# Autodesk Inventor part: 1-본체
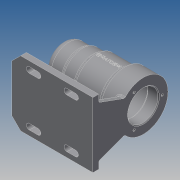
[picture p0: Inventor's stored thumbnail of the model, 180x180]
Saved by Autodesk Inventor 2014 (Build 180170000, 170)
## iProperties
Created: 2017-09
Part Number: 1-본체
Material: Generic
Document SubType Name: Modeling
Designer: kb542-00
Density: 1 g/cm^3
Appearance: Default
Author: kb542-00
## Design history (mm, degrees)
sketch "스케치1"
  geometry: L1 (-112, 0)-(0, 0); L2 (0, 21)-(0, 34); L3 (0, 34)-(-28, 34); L4 (-28, 34)-(-28, 30); L5 (-28, 30)-(-67, 30); L6 (-67, 30)-(-67, 27); L7 (-67, 27)-(-87, 27); L8 (-87, 27)-(-87, 25); L9 (-87, 25)-(-112, 25); L10 (-112, 25)-(-112, 0); L11 (-106, 0)-(-106, 10.5); L12 (-106, 10.5)-(-103, 10.5); L13 (-103, 10.5)-(-103, 16); L14 (-103, 16)-(-99, 16); L15 (-99, 16)-(-99, 17.5); L16 (-99, 17.5)-(-81, 17.5); L17 (-81, 17.5)-(-81, 21); L18 (-81, 21)-(-69, 21); L19 (-69, 21)-(-69, 24); L20 (-69, 24)-(-15, 24); L21 (-15, 24)-(-15, 21); L22 (-15, 21)-(0, 21); 1 further point
  constraints: 44 end point, 15 parallel, 6 perpendicular, 1 coincident, 1 horizontal, 1 point on line, 1 vertical alignment
  dimensions: "d0" = 68 diameter of L3 L1; "d1" = 42 diameter of L22 L1; "d2" = 112 distance between parallel lines of L2 L10; "d3" = 25 distance between parallel lines of L8 L10; "d4" = 45 distance between parallel lines of L6 L10; "d5" = 84 distance between parallel lines of L4 L10; "d6" = 48 diameter of L20 L1; "d7" = 15 distance between parallel lines of L2 L21; "d8" = 42 diameter of L18 L1; "d9" = 3 distance between parallel lines of L13 L11; "d10" = 4 distance between parallel lines of L15 L13; "d11" = 18 distance between parallel lines of L17 L15; "d12" = 12 distance between parallel lines of L19 L17; "d13" = 54 distance between parallel lines of L21 L19; "d14" = 21 diameter of L12 L1; "d15" = 32 diameter of L14 L1; "d16" = 35 diameter of L16 L1; "d17" = 50 diameter of L9 L1; "d18" = 54 diameter of L7 L1; "d19" = 60 diameter of L5 L1
revolve "회전1" sketch "스케치1" stored, may be unused: angle "d20" = 90 deg
fillet "모깎기1" dims "d21" = 9
node "작업 평면1"
sketch "스케치2"
  geometry: L1 (0, 45)-(100, 45); L2 (112, 33)-(112, -33); L3 (100, -45)-(0, -45); L4 (0, -45)-(0, 45); L5 (100, 45)-(112, 33); L6 (112, -33)-(100, -45); L7 (24, 34)-(36, 34); L8 (24, 30)-(36, 30); L9 (36, 38)-(24, 38); L10 (76, 34)-(88, 34); L11 (76, 30)-(88, 30); L12 (88, 38)-(76, 38); L13 (24, -34)-(36, -34); L14 (24, -38)-(36, -38); L15 (36, -30)-(24, -30); L16 (76, -34)-(88, -34); L17 (76, -38)-(88, -38); L18 (88, -30)-(76, -30); A1 r 4 centre (24, 34) between (24, 38) and (24, 30); A2 r 4 centre (36, 34) between (36, 30) and (36, 38); A3 r 4 centre (76, 34) between (76, 38) and (76, 30); A4 r 4 centre (88, 34) between (88, 30) and (88, 38); A5 r 4 centre (24, -34) between (24, -30) and (24, -38); A6 r 4 centre (36, -34) between (36, -38) and (36, -30); A7 r 4 centre (76, -34) between (76, -30) and (76, -38); A8 r 4 centre (88, -34) between (88, -38) and (88, -30); 8 further points
  constraints: 44 end point, 16 point on circle, 16 tangent, 9 parallel, 8 centre point, 5 midpoint, 4 point on line, 2 vertical alignment, 1 coincident, 1 horizontal, 1 perpendicular
  dimensions: "d25" = 90 distance between parallel lines of L3 L1; "d26" = 112 distance between parallel lines of L2 L4; "d27" = 12 distance of L1.end point (112, 45); "d28" = 12 distance of L2.start point (112, 45) (= d27); "d29" = 12 distance of L2.end point (112, -45) (= d27); "d30" = 12 distance of L3.start point (112, -45) (= d29); "d31" = 34 vertical distance of point (0, 0) L7.start; "d32" = 34 vertical distance of point (0, 0) L13.start; "d33" = 4 radius of A1; "d34" = 4 radius of A3; "d35" = 4 radius of A6; "d36" = 4 radius of A8; "d37" = 12 distance of L13.end L13.start; "d38" = 12 distance of L7.end L7.start; "d39" = 12 distance of L10.end L10.start; "d40" = 12 distance of L16.end L16.start; "d41" = 24 distance from line of L7.start L4; "d42" = 24 distance from line of L13.start L4; "d43" = 34 vertical distance of point (0, 0) L16.end; "d44" = 34 vertical distance of point (0, 0) L10.end; "d45" = 40 distance of L7.end L10.start; "d46" = 40 distance of L16.start L13.end
extrude "돌출1" join sketch "스케치2" distance "d47" = 8; taper "d48" = 0 deg
sketch "스케치3"
  geometry: L1 (-103, 25)-(-87, 25) reference; L2 (-87, 25)-(-87, 27) reference; L3 (-87, 27)-(-67, 27) reference; L4 (-67, 27)-(-67, 30) reference; L5 (-67, 30)-(-28, 30) reference; L6 (-28, 30)-(-28, 34) reference; L7 (-28, 34)-(0, 34) reference; L8 (0, 34)-(0, 21) reference; L9 (0, 21)-(-15, 21) reference; L10 (-15, 21)-(-15, 24) reference; L11 (-15, 24)-(-69, 24) reference; L12 (-69, 24)-(-69, 21) reference; L13 (-69, 21)-(-81, 21) reference; L14 (-81, 21)-(-81, 17.5) reference; L15 (-81, 17.5)-(-99, 17.5) reference; L16 (-99, 17.5)-(-99, 16) reference; L17 (-99, 16)-(-103, 16) reference; L18 (-103, 16)-(-103, 10.5) reference; L19 (-103, 10.5)-(-106, 10.5) reference; L20 (-106, 10.5)-(-106, -10.5) reference; L21 (-106, -10.5)-(-103, -10.5) reference; L22 (-103, -10.5)-(-103, -16) reference; L23 (-103, -16)-(-99, -16) reference; L24 (-99, -16)-(-99, -17.5) reference; L25 (-99, -17.5)-(-81, -17.5) reference; L26 (-81, -17.5)-(-81, -21) reference; L27 (-81, -21)-(-69, -21) reference; L28 (-69, -21)-(-69, -24) reference; L29 (-69, -24)-(-15, -24) reference; L30 (-15, -24)-(-15, -21) reference; L31 (-15, -21)-(0, -21) reference; L32 (0, -21)-(0, -34) reference; L33 (0, -34)-(-28, -34) reference; L34 (-28, -34)-(-28, -30) reference; L35 (-28, -30)-(-67, -30) reference; L36 (-67, -30)-(-67, -27) reference; L37 (-67, -27)-(-87, -27) reference; L38 (-87, -27)-(-87, -25) reference; L39 (-87, -25)-(-103, -25) reference; L40 (-112, -16)-(-112, 16) reference; L41 (0, -62)-(0, -70) reference; L42 (0, -70)-(-112, -70) reference; L43 (-112, -70)-(-112, -62) reference; L44 (-112, -62)-(0, -62) reference; L45 (0, -62)-(-100, -62) reference; L46 (-90, -62)-(-80.622, -27); A1 r 9 centre (-103, 16) between (-103, 25) and (-112, 16) reference; A2 r 9 centre (-103, -16) between (-112, -16) and (-103, -25) reference; 1 further point
  constraints: 2 end point, 2 point on line
  dimensions: "d49" = 105 deg angle of L46 L45; "d50" = 22 distance from line of L46.start L43
  node "절단 모서리 투영1"
sketch "스케치7"
  geometry: L1 (-70, 45)-(-62, 45) reference; L2 (-62, 45)-(-62, -45) reference; L3 (-62, -45)-(-70, -45) reference; L4 (-70, -45)-(-70, 45) reference; L5 (-26.008, 21.9)-(-62, 35); L6 (-62, 45)-(-62, -45) reference; L7 (-26.008, -21.9)-(-62, -35); L8 (-62, -35)-(-62, 35); C1 r 21 at (0, 0) reference; C2 r 16 at (0, 0) reference; C3 r 34 at (0, 0); A1 r 34 centre (0, 0) between (-26.008, 21.9) and (-26.008, -21.9) reference; A2 r 34 centre (0, 0) between (-26.008, 21.9) and (-26.008, -21.9) reference; A3 r 34 centre (0, 0) between (-26.008, 21.9) and (-26.008, -21.9); 1 further point
  constraints: 6 end point, 6 point on circle, 2 centre point, 2 coincident, 2 point on line, 1 collinear
  dimensions: "d63" = 110 deg angle of L6 L7; "d64" = 110 deg angle of L2 L5; "d65" = 10 distance from line of L5.end L1; "d66" = 10 distance from line of L3 L7.end
extrude "돌출2" join sketch "스케치7" distance "d68" = 8; taper "d69" = 0 deg
feature "리브1" dims "d70" = 1, "d71" = 8, "d72" = 0, "d73" = 0, "d74" = 1, "d75" = 1
sketch "스케치8" dims "d76" = 52
  geometry: C1 r 21 at (45, 70) reference; A1 r 34 centre (45, 70) between (66.9, 43.992) and (23.1, 43.992) reference; 2 further points
  constraints: 2 vertical alignment, 1 coincident, 2 other
hole "구멍1" sketch "스케치8" at (45, 96) diameter "d77" = 3.242; stored, may be unused: countersink angle "d81" = 90 deg, drill point angle "d83" = 118 deg; dims "d78" = 8, "d79" = 4, "d80" = 2, "d82" = 11
chamfer "모따기1" distance "d87" = 1; stored, may be unused: second distance "d88" = 2, angle "d89" = 45 deg
fillet "모깎기2" dims "d90" = 0.3
fillet "모깎기3" dims "d91" = 3
fillet "모깎기4" dims "d92" = 3
node "작업 평면3"
sketch "스케치9"
  geometry: L1 (47.5, -24.711)-(47.5, 34) reference; 2 further points
  constraints: 1 horizontal alignment, 1 other
  dimensions: "d94" = 48 distance from line of point (-0.5, 0) L1
feature "엠보싱1" sketch "스케치9" dims "d0" = 68, "d1" = 42, "d2" = 112, "d3" = 25, "d4" = 45, "d5" = 84, "d6" = 48, "d7" = 15, "d8" = 42, "d9" = 3, "d10" = 4, "d11" = 18, "d12" = 12, "d13" = 54, "d14" = 21, "d15" = 32, "d16" = 35, "d17" = 50, "d18" = 54, "d19" = 60, "d95" = 0.5, "d96" = 0
fillet "모깎기5" dims "d97" = 3
node "솔리드1"
pattern_circular "원형 패턴1" dims angle "d85" = 360 deg
node "절단 모서리 투영4"
